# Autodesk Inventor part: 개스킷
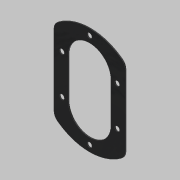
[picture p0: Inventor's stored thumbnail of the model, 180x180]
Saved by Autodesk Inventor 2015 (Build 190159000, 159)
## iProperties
Created: 2019-03
Part Number: 개스킷
Material: 고무
Document SubType Name: Modeling
Designer: mduedu
Density: 1 g/cm^3
Appearance: 고무 - 검은색 - 버전 1.1
Author: mduedu
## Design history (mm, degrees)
sketch "스케치1"
  geometry: L1 (-44.721, -40)-(44.721, -40); L2 (44.721, 40)-(-44.721, 40); A1 r 60 centre (0, 0) between (44.721, -40) and (44.721, 40); A2 r 60 centre (0, 0) between (-44.721, 40) and (-44.721, -40); 5 further points
  constraints: 6 point on circle, 4 end point, 2 centre point, 2 coincident, 2 horizontal alignment, 2 midpoint, 2 vertical alignment, 1 horizontal, 1 parallel
  dimensions: "d0" = 60 radius of A1; "d2" = 80 distance between parallel lines of L2 L1
extrude "돌출1" new body sketch "스케치1" distance "d3" = 1; taper "d4" = 0 deg
fillet "모깎기1" dims "d5" = 10
sketch "스케치2" dims "d6" = 48
  geometry: L1 (-24, -22)-(24, -22); L2 (24, -22)-(24, 22); L3 (24, 22)-(-24, 22); L4 (-24, 22)-(-24, -22); L5 (-24, -22)-(24, 22); L6 (24, -22)-(-24, 22); 3 further points
  constraints: 12 end point, 4 midpoint, 2 horizontal alignment, 2 parallel, 1 horizontal, 1 perpendicular, 4 other
  dimensions: "d8" = 22 distance from line of L3 point (0, 0)
extrude "돌출2" cut sketch "스케치2" stored distance "d9" = 1; taper "d10" = 0 deg
sketch "스케치3" dims "d0" = 60, "d2" = 80
  geometry: L1 (31, -22)-(31, 22); L2 (-31, 22)-(-31, -22); L3 (-31, -22)-(31, 22); L4 (31, -22)-(-31, 22); A1 r 31 centre (0, 22) between (31, 22) and (-31, 22); A2 r 31 centre (0, -22) between (-31, -22) and (31, -22); 8 further points
  constraints: 8 end point, 6 point on circle, 4 coincident, 4 midpoint, 3 tangent, 2 centre point, 2 vertical alignment, 1 parallel
  dimensions: "d11" = 31 radius of A1; "d13" = 44 distance of A2.centre A1.centre
hole "구멍1" sketch "스케치3" at (-31, 22), (-31, -22), (31, -22), (31, 22), (0, -53), (0, 53) diameter "d14" = 5.5; stored, may be unused: countersink angle "d18" = 90 deg, drill point angle "d20" = 118 deg; dims "d15" = 6, "d16" = 4, "d17" = 2, "d19" = 8
node "솔리드1"
